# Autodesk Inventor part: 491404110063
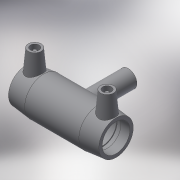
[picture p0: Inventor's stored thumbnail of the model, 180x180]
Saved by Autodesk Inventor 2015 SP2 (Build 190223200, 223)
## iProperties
Created: 2017-06
Part Number: 491404110063
Material: Generic
Description: PLASSON REDUCING TEE 110x63x110
Document SubType Name: Modeling
Designer: KIM
Mass: 57.3761 g
Surface Area: 241.06 cm^2
Volume: 57.3761 cm^3
Density: 1 g/cm^3
Appearance: Default
Author: KIM
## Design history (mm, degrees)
derived "491404.ipt"
feature "Solid1::491404.ipt"
tag "TaggingFeature1"
body "Solid1"
other parameters: "d0" = 326, "d2" = 143, "d3" = 71, "d4" = 65.2, "d5" = 128.7, "d6" = 104.5, "d8" = 168 deg, "d10" = 28.4, "d11" = 9.46667, "d13" = 326, "d14" = 17.6296, "d17" = 99, "d19" = 3.52592, "d20" = 168 deg, "d22" = 132.99, "d23" = 143, "d25" = 135 deg, "d26" = 228.2, "d29" = 81, "d30" = 15, "d31" = 130.4, "d34" = 5 deg, "d35" = 15, "d39" = 5 deg, "d41" = 4, "d42" = 14, "d43" = 0, "d45" = 4, "d46" = 6, "d47" = 0, "d48" = -134, "d49" = 63, "d51" = 0, "d52" = 50.4, "d54" = 0, "d55" = 128.7, "d56" = 143, "d57" = 114.1, "d58" = 135 deg, "d59" = 71, "d60" = 71, "d61" = 135 deg, "d62" = 134, "d72" = 148.33, "d73" = 74.165, "d74" = -134, "d75" = 66.15, "d77" = 0, "d78" = 50.4, "d80" = 0, "d81" = 63, "d82" = 62.5, "d83" = 0, "d84" = 3, "d85" = 0, "d86" = 23.66667, "d87" = 130.3302, "d88" = 9.46667, "d89" = 3, "d90" = 0, "L_" = 326, "L_1" = 71, "D_" = 143, "A_" = 81, "d_2" = 12, "H_" = 134, "d_1" = 63
